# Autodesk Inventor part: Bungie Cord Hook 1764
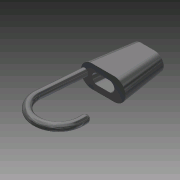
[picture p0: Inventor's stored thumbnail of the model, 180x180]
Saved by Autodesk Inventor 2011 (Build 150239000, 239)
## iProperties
Created: 2009-02
Part Number: Bungie Cord Hook 1764
Document SubType Name: Modeling
Designer: jrobinson
Density: 1 g/cm^3
Author: jrobinson
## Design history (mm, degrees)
sketch "Sketch1"
  geometry: L1 (-14.061, -5.266)-(-33.111, -5.266); L2 (-33.111, 13.784)-(-14.061, 13.784); A1 r 9.525 centre (-14.061, 4.259) between (-14.061, -5.266) and (-14.061, 13.784); A2 r 9.525 centre (-33.111, 4.259) between (-33.111, 13.784) and (-33.111, -5.266)
  constraints: 4 end point, 4 point on circle, 2 centre point, 1 horizontal, 1 parallel
  dimensions: "d0" = 19.05 diameter of A2; "d1" = 19.05 distance of A2.centre A1.centre
workplane "Work Plane1"
workplane "Work Plane2"
sketch "Sketch2"
  geometry: L1 (3.487, 17.145)-(15.563, 17.145); L2 (15.563, 1.905)-(3.487, 1.905); A1 r 7.62 centre (3.487, 9.525) between (3.487, 17.145) and (3.487, 1.905); A2 r 7.62 centre (15.563, 9.525) between (15.563, 1.905) and (15.563, 17.145)
  constraints: 4 end point, 4 point on circle, 2 centre point, 1 horizontal, 1 parallel
  dimensions: "d3" = 15.24 diameter of A1
loft "Loft1" sketch "Sketch2" dims "d4" = 0, "d5" = 90 deg, "d6" = 0, "d7" = 90 deg
sketch "Sketch3"
  geometry: L1 (4.445, -5.08)-(14.605, -5.08); L2 (14.605, -13.97)-(4.445, -13.97); A1 r 9.525 centre (0, -9.525) between (0, 0) and (0, -19.05) reference; A2 r 9.525 centre (19.05, -9.525) between (19.05, -19.05) and (19.05, 0) reference; A3 r 4.445 centre (4.445, -9.525) between (4.445, -5.08) and (4.445, -13.97); A4 r 4.445 centre (14.605, -9.525) between (14.605, -13.97) and (14.605, -5.08)
  constraints: 6 point on circle, 4 end point, 3 tangent, 2 centre point, 1 equal radius
  dimensions: "d8" = 8.89 diameter of A3
sketch "Sketch4"
  geometry: C1 r 4.445 at (6.038, -7.62)
  constraints: 1 centre point
  dimensions: "d9" = 8.89 diameter of C1
loft "Loft2" sketch "Sketch3", "Sketch4" dims "d10" = 0, "d11" = 90 deg, "d12" = 0, "d13" = 90 deg
sketch "Sketch5"
  geometry: C1 r 3.175 at (-6.35, -9.525); A1 r 9.525 centre (0, -9.525) between (0, 0) and (0, -19.05) reference
  constraints: 1 centre point, 1 tangent
  dimensions: "d14" = 6.35 diameter of C1
workplane "Work Plane3"
sketch "Sketch6"
  geometry: 2 further points
  constraints: 2 horizontal alignment, 3 other
loft "Loft3" sketch "Sketch6" dims "d16" = 0, "d17" = 90 deg, "d18" = 0, "d19" = 90 deg
workplane "Work Plane4"
sketch "Sketch7"
  geometry: L1 (9.525, 22.86)-(9.525, -3.81) reference; C1 r 3.175 at (28.575, 9.525) reference; C2 r 3.175 at (-9.525, 9.525)
  constraints: 1 centre point, 1 symmetric about line, 1 other
revolve "Revolution1" sketch "Sketch7" stored, may be unused: angle "d20" = 180 deg
sketch "Sketch8"
  geometry: C1 r 3.175 at (0, 0) reference
extrude "Extrusion1" join sketch "Sketch8" distance "d21" = 6.35; taper "d22" = 0 deg
fillet "Fillet1" dims "d23" = 3.175
body "Solid1"
node "Projected Loop1"
other parameters: "d2" = 38.1, "d15" = -38.1
